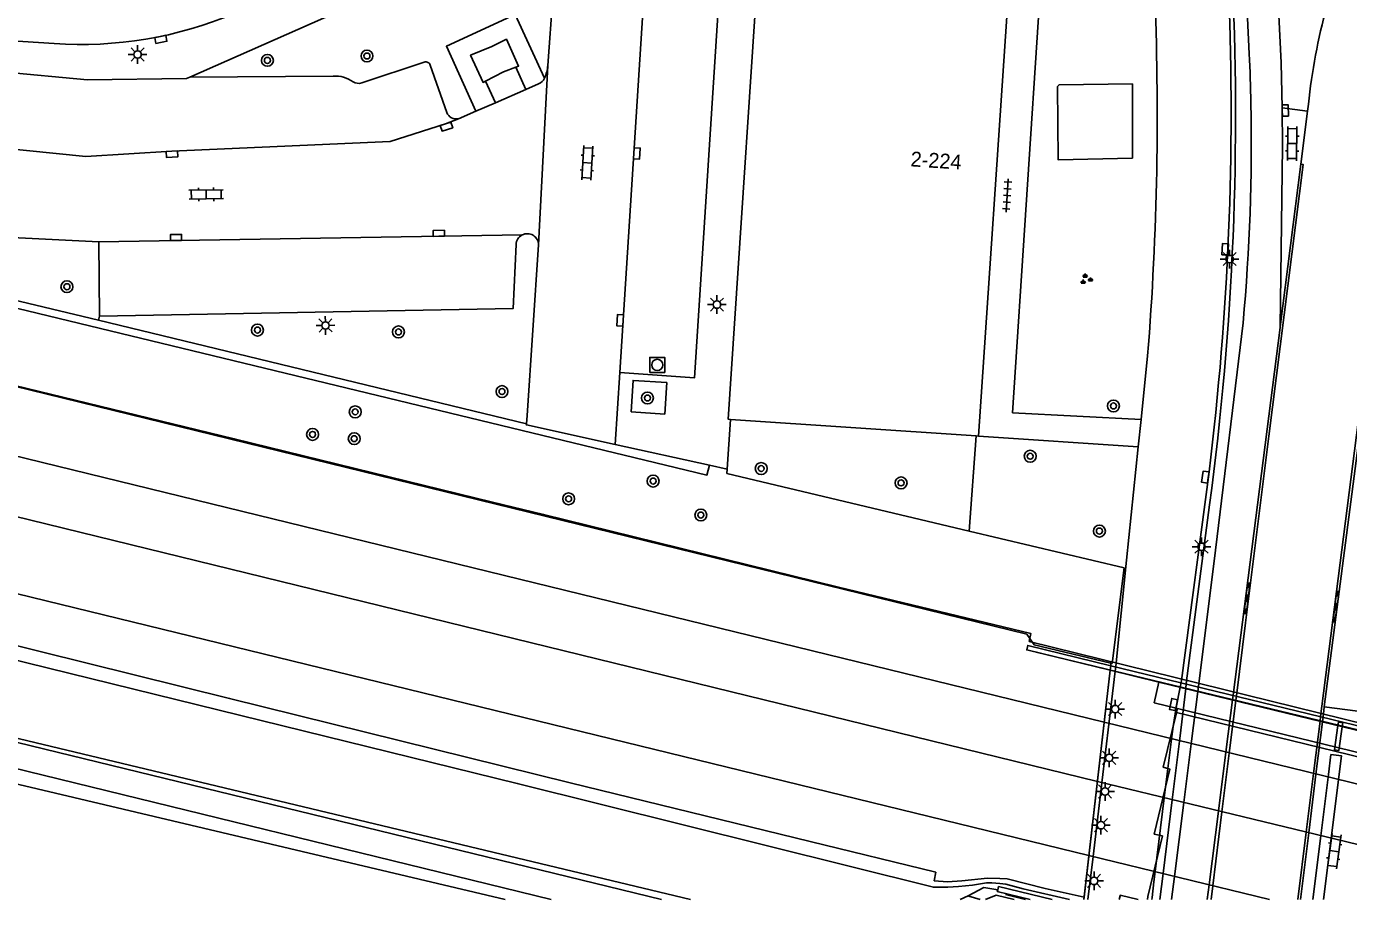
# Model space of a CAD drawing. Extents: x 132998 to 136004, y 396998 to 398512.
# Drawn here: x 133226.6 to 133315.3, y 397000 to 397058.6 of the extents above; entities that cross this region are included whole.
import ezdxf

# ---------------------------------------------------------------- set-up
doc = ezdxf.new("R2010")
doc.units = 0
for name, color, linetype in [('gg-afsc-hekwerk', 7, 'Continuous'), ('gg-afsc-muur', 7, 'Continuous'), ('gg-anno-huisnummerreeks BGT', 7, 'Continuous'), ('gg-aspt-spoorlijn', 7, 'Continuous'), ('gg-bbg-hoofdgebouw', 7, 'Continuous'), ('gg-bbg-lage trafo', 7, 'Continuous'), ('gg-bbg-pilaar viaduct of brug', 7, 'Continuous'), ('gg-knt-BGT kruinlijn', 7, 'Continuous'), ('gg-knt-bovenkant onderkant talud', 7, 'Continuous'), ('gg-knt-bronhoudergrens', 7, 'Continuous'), ('gg-knt-verharding', 7, 'Continuous'), ('gg-knt-verharding niveau 01', 7, 'Continuous'), ('gg-knt-verharding nz', 7, 'Continuous'), ('gg-kntw-beschoeiing', 7, 'Continuous'), ('gt-grn-afwateringsgoot', 7, 'Continuous'), ('gt-grn-bladgrens', 7, 'Continuous'), ('gt-grn-groengrens', 7, 'Continuous'), ('gt-grn-weggrens', 7, 'Continuous'), ('gt-symb-afwateringsgoot', 7, 'Continuous'), ('gt-symb-boom', 7, 'Continuous'), ('gt-symb-groenvak', 7, 'Continuous'), ('gt-symb-klinker verharding', 7, 'Continuous'), ('gt-symb-kolk', 7, 'Continuous'), ('gt-symb-lichtmast', 7, 'Continuous'), ('gt-symb-rioolschacht', 7, 'Continuous'), ('gt-symb-tegel verharding', 7, 'Continuous'), ('gx-grn-maaiveld', 7, 'Continuous'), ('gx-knt-lijn weginrichtingselement', 7, 'Continuous')]:
    doc.layers.add(name, color=color, linetype=linetype)

# ---------------------------------------------------------------- blocks, each defined once
blk = doc.blocks.new('gt0-BOOM')
at = {"layer": 'gt-symb-boom'}
for radius in [0.4, 0.2]:
    blk.add_circle((0, 0), radius, dxfattribs=at)
blk = doc.blocks.new('gt0-LMAST')
at = {"layer": 'gt-symb-lichtmast'}
for p, q in [((-0.182, 0.173), (-0.447, 0.438)), ((-0.005, 0.246), (-0.005, 0.621)), ((0.172, 0.173), (0.437, 0.438)), ((-0.255, -0.004), (-0.63, -0.004)), ((-0.182, -0.181), (-0.447, -0.446)), ((-0.005, -0.254), (-0.005, -0.629)), ((0.437, -0.446), (0.172, -0.181)), ((0.245, -0.004), (0.62, -0.004))]:
    blk.add_line(p, q, dxfattribs=at)
blk.add_circle((-0.005, -0.004), 0.25, dxfattribs=at)
blk = doc.blocks.new('gt0-KOLK')
at = {"layer": 'gt-symb-kolk'}
blk.add_lwpolyline([(0, 0), (0.375, 0), (0.375, 0.4), (-0.375, 0.4), (-0.375, 0), (0, 0)], dxfattribs=at)
blk = doc.blocks.new('gt0-KL1')
at = {"layer": 'gt-symb-klinker verharding'}
for p, q in [((-1.15, 0.3), (1.15, 0.3)), ((-1, -0.3), (-1, 0.3)), ((-0.5, 0.3), (-0.5, 0.45)), ((0, -0.3), (0, 0.3)), ((0.5, 0.3), (0.5, 0.45)), ((1, -0.3), (1, 0.3)), ((-1.15, -0.3), (1.15, -0.3)), ((-0.5, -0.45), (-0.5, -0.3)), ((0.5, -0.45), (0.5, -0.3))]:
    blk.add_line(p, q, dxfattribs=at)
blk = doc.blocks.new('gt0-RS')
at = {"layer": 'gt-symb-rioolschacht'}
blk.add_lwpolyline([(-0.5, -0.5), (0.5, -0.5), (0.5, 0.5), (-0.5, 0.5)], close=True, dxfattribs=at)
blk.add_circle((0, 0), 0.375, dxfattribs=at)
blk = doc.blocks.new('gt0-TEG1')
at = {"layer": 'gt-symb-tegel verharding'}
for p, q in [((-1.125, 0), (1.125, 0)), ((-0.9, -0.25), (-0.9, 0.25)), ((-0.45, -0.25), (-0.45, 0.25)), ((0, -0.25), (0, 0.25)), ((0.45, -0.25), (0.45, 0.25)), ((0.9, -0.25), (0.9, 0.25))]:
    blk.add_line(p, q, dxfattribs=at)
blk = doc.blocks.new('gt0-GRVAK')
at = {"layer": 'gt-symb-groenvak'}
for p, q in [((-0.11, 0.189), (-0.228, 0.24)), ((-0.182, 0.153), (0.088, 0.153)), ((-0.091, 0.211), (-0.156, 0.322)), ((-0.047, 0.214), (-0.047, 0.393)), ((-0.004, 0.211), (0.061, 0.322)), ((0.015, 0.189), (0.133, 0.24)), ((0.262, -0.052), (0.197, 0.059)), ((0.305, -0.049), (0.305, 0.13)), ((0.349, -0.052), (0.414, 0.059)), ((-0.245, -0.228), (-0.363, -0.177)), ((-0.318, -0.264), (-0.047, -0.264)), ((-0.226, -0.206), (-0.291, -0.095)), ((-0.183, -0.203), (-0.183, -0.024)), ((-0.139, -0.206), (-0.074, -0.095)), ((-0.12, -0.228), (-0.002, -0.177)), ((0.243, -0.074), (0.125, -0.023)), ((0.17, -0.11), (0.441, -0.11)), ((0.368, -0.074), (0.486, -0.023))]:
    blk.add_line(p, q, dxfattribs=at)
blk = doc.blocks.new('gt0-AFWGT_1')
at = {"layer": 'gt-symb-afwateringsgoot'}
for p, q in [((-1.076, 0), (-0.726, 0)), ((-0.225, 0), (0.225, 0)), ((0.725, 0), (1.075, 0))]:
    blk.add_line(p, q, dxfattribs=at)
for points in [[(-0.726, 0.075), (-0.225, 0.075), (-0.225, -0.075), (-0.726, -0.075)], [(0.225, 0.075), (0.725, 0.075), (0.725, -0.075), (0.225, -0.075)]]:
    blk.add_lwpolyline(points, close=True, dxfattribs=at)

msp = doc.modelspace()

# ---------------------------------------------------------------- linework, layer by layer
at = {"layer": 'gg-afsc-hekwerk'}
for p, q in [((133273.86, 397032.22), (133273.639, 397028.884)), ((133273.86, 397032.22), (133273.639, 397028.884)), ((133289.871, 397024.728), (133290.35, 397031.11)), ((133289.871, 397024.728), (133290.35, 397031.11)), ((133273.639, 397028.884), (133273.619, 397028.578)), ((133273.639, 397028.884), (133273.619, 397028.578)), ((133273.619, 397028.578), (133289.871, 397024.728)), ((133273.619, 397028.578), (133289.871, 397024.728)), ((133300.273, 397022.263), (133289.871, 397024.728)), ((133300.273, 397022.263), (133289.871, 397024.728)), ((133300.273, 397022.263), (133299.472, 397015.831)), ((133300.273, 397022.263), (133299.472, 397015.831))]:
    msp.add_line(p, q, dxfattribs=at)
msp.add_lwpolyline([(133000, 397065.503), (133076.543, 397046.781), (133180.571, 397021.692), (133271.17, 397000)], dxfattribs=at)
msp.add_lwpolyline([(133000, 397065.503), (133076.543, 397046.781), (133180.571, 397021.692), (133271.17, 397000)], dxfattribs=at)
at = {"layer": 'gg-afsc-muur'}
for p, q in [((133293.74, 397017.818), (133163.478, 397049.706)), ((133293.74, 397017.818), (133163.478, 397049.706)), ((133305.964, 397028.691), (133304.112, 397014.708)), ((133304.438, 397014.491), (133305.998, 397026.478)), ((133304.411, 397014.163), (133303.997, 397010.814)), ((133304.025, 397014.258), (133304.094, 397014.575)), ((133304.112, 397014.708), (133304.094, 397014.575)), ((133304.438, 397014.491), (133304.411, 397014.163)), ((133302.958, 397006.824), (133303.477, 397010.94)), ((133303.49, 397006.695), (133303.997, 397010.814)), ((133302.343, 397001.873), (133302.958, 397006.824)), ((133303.49, 397006.695), (133302.878, 397001.741)), ((133302.663, 397000), (133302.878, 397001.741)), ((133302.122, 397000), (133302.138, 397000.144))]:
    msp.add_line(p, q, dxfattribs=at)
for points in [[(133303.477, 397010.94), (133303.562, 397011.622), (133303.748, 397012.891), (133304.025, 397014.258)], [(133302.138, 397000.144), (133302.257, 397001.18), (133302.343, 397001.873)]]:
    msp.add_lwpolyline(points, dxfattribs=at)
for centre, radius, start, end in [((133111.617, 397052.578), 196.126, 352.35237, 2.92485), ((133109.549, 397052.867), 197.897, 352.98297, 2.3061)]:
    msp.add_arc(centre, radius, start, end, dxfattribs=at)
at = {"layer": 'gg-aspt-spoorlijn'}
for p, q in [((133000, 397081.027), (133298.474, 397007.929)), ((133298.931, 397011.894), (133329.558, 397004.427)), ((133298.474, 397007.929), (133329.088, 397000.493)), ((133297.901, 397002.954), (133310.014, 397000))]:
    msp.add_line(p, q, dxfattribs=at)
for points in [[(133000, 397085.097), (133023.788, 397079.291), (133131.609, 397052.829), (133298.931, 397011.894)], [(133000, 397075.839), (133096.746, 397052.101), (133297.901, 397002.954)]]:
    msp.add_lwpolyline(points, dxfattribs=at)
at = {"layer": 'gg-bbg-hoofdgebouw'}
for p, q in [((133292.952, 397067.526), (133290.5, 397031.1)), ((133273.86, 397032.22), (133290.35, 397031.11)), ((133290.35, 397031.11), (133290.5, 397031.1))]:
    msp.add_line(p, q, dxfattribs=at)
msp.add_lwpolyline([(133276.14, 397069.07), (133273.71, 397032.23), (133273.86, 397032.22)], dxfattribs=at)
at = {"layer": 'gg-bbg-lage trafo'}
for points in [[(133259.457, 397055.854), (133259.647, 397055.925), (133258.834, 397057.729), (133257.856, 397057.237), (133256.43, 397056.648), (133257.26, 397054.831), (133257.433, 397054.921)], [(133257.433, 397054.921), (133258.635, 397055.545), (133259.457, 397055.854)]]:
    msp.add_lwpolyline(points, dxfattribs=at)
at = {"layer": 'gg-bbg-pilaar viaduct of brug'}
for p, q in [((133313.466, 397004.274), (133313.979, 397008.401)), ((133314.161, 397004.106), (133314.674, 397008.233)), ((133312.935, 397000), (133313.466, 397004.274)), ((133313.651, 397000), (133314.161, 397004.106))]:
    msp.add_line(p, q, dxfattribs=at)
for points in [[(133314.611, 397011.673), (133314.377, 397010.05), (133314.674, 397010.007), (133314.904, 397011.601)], [(133314.611, 397011.673), (133314.644, 397011.9), (133314.941, 397011.857), (133314.904, 397011.601)], [(133314.674, 397008.233), (133314.849, 397009.645), (133314.145, 397009.733), (133313.979, 397008.401)]]:
    msp.add_lwpolyline(points, dxfattribs=at)
at = {"layer": 'gg-knt-BGT kruinlijn'}
msp.add_lwpolyline([(133186.49, 397000), (133184.153, 397003.644), (133183.522, 397004.975), (133183.374, 397006.047), (133183.716, 397010.358), (133184.658, 397013.497), (133185.793, 397015.048), (133187.27, 397015.648), (133189.046, 397016.11), (133191.787, 397015.743), (133224.019, 397008.202), (133258.747, 397000)], dxfattribs=at)
at = {"layer": 'gg-knt-bovenkant onderkant talud'}
msp.add_line((133291.681, 397000.298), (133292.893, 397000), dxfattribs=at)
at = {"layer": 'gg-knt-bronhoudergrens'}
msp.add_line((133299.387, 397015.852), (133299.472, 397015.831), dxfattribs=at)
msp.add_lwpolyline([(133293.74, 397017.818), (133294.231, 397017.101), (133299.387, 397015.852)], dxfattribs=at)
at = {"layer": 'gg-knt-verharding'}
for p, q in [((133307.747, 397075.693), (133308.664, 397056.751)), ((133261.606, 397055.966), (133262.269, 397064.966)), ((133257.999, 397064.195), (133237.59, 397055.191)), ((133292.79, 397032.65), (133294.805, 397063.341)), ((133219.287, 397058.019), (133228.484, 397057.43)), ((133249.131, 397054.792), (133253.321, 397056.187)), ((133253.723, 397055.994), (133254.834, 397052.81)), ((133260.134, 397054.35), (133259.457, 397055.854)), ((133237.59, 397055.191), (133247.208, 397055.244)), ((133258.088, 397053.462), (133257.433, 397054.921)), ((133258.088, 397053.462), (133260.134, 397054.35)), ((133260.134, 397054.35), (133260.99, 397054.734)), ((133256.775, 397052.901), (133258.088, 397053.462)), ((133312.568, 397052.89), (133312.627, 397053.366)), ((133255.606, 397052.389), (133256.775, 397052.901)), ((133312.568, 397052.89), (133310.87, 397053.129)), ((133312.133, 397049.349), (133312.568, 397052.89)), ((133310.739, 397038.43), (133312.133, 397049.349)), ((133231.483, 397044.133), (133231.53, 397039.14)), ((133260.213, 397032.483), (133260.983, 397043.922)), ((133301.845, 397036.477), (133301.403, 397032.218)), ((133266.131, 397030.538), (133266.441, 397035.367)), ((133260.175, 397031.922), (133260.213, 397032.483)), ((133292.79, 397032.65), (133301.403, 397032.218)), ((133301.403, 397032.218), (133301.213, 397030.379)), ((133290.5, 397031.1), (133301.213, 397030.379)), ((133316.126, 397031.677), (133313.693, 397012.921)), ((133272.447, 397029.147), (133266.131, 397030.538)), ((133273.639, 397028.884), (133272.447, 397029.147)), ((133313.693, 397012.921), (133313.61, 397012.245)), ((133313.693, 397012.921), (133317.712, 397012.407))]:
    msp.add_line(p, q, dxfattribs=at)
for points in [[(133309.826, 397076.336), (133309.845, 397075.81), (133310.793, 397056.152), (133310.87, 397053.129)], [(133000, 397064.614), (133037.586, 397055.47), (133127.872, 397033.617), (133162.421, 397025.507), (133179.236, 397021.338), (133188.591, 397019.265), (133225.122, 397010.768), (133269.223, 397000)], [(133268.243, 397063.458), (133273.262, 397063.183), (133271.438, 397035.006), (133266.441, 397035.367)], [(133256.775, 397052.901), (133254.808, 397057.253), (133259.408, 397059.39), (133261.382, 397055.116)], [(133237.59, 397055.191), (133237.36, 397055.09), (133230.74, 397055), (133201.968, 397057.692), (133201.842, 397056.086)], [(133310.87, 397053.129), (133310.902, 397050.534), (133310.739, 397038.43)], [(133231.483, 397044.133), (133224.75, 397044.46), (133197.779, 397047.017)], [(133231.53, 397039.14), (133259.28, 397039.65), (133259.48, 397043.951)], [(133308.248, 397038.702), (133306.405, 397023.437), (133305.25, 397014.292)], [(133307.591, 397013.719), (133310.732, 397038.377), (133310.739, 397038.43)], [(133267.196, 397032.719), (133267.331, 397034.835), (133269.582, 397034.687), (133269.447, 397032.571), (133267.196, 397032.719)], [(133266.131, 397030.538), (133260.17, 397031.85), (133260.175, 397031.922)], [(133301.213, 397030.379), (133300.425, 397022.783), (133299.711, 397015.65)], [(133180.087, 397016.001), (133180.812, 397017.737), (133181.256, 397018.408), (133182.146, 397018.674), (133187.675, 397017.479), (133224.542, 397009.119), (133261.83, 397000)]]:
    msp.add_lwpolyline(points, dxfattribs=at)
for centre, radius, start, end in [((133098.931, 397052.639), 203.556, 355.44591, 2.44072), ((133230.246, 397084.159), 26.787, 266.22854, 292.66688), ((133354.833, 397048.833), 42.449, 164.89429, 173.86958), ((133176.205, 397050.826), 132.592, 1.12284, 2.56129), ((133253.428, 397055.894), 0.312, 18.66912, 110.0396), ((133259.234, 397056.136), 2.378, 334.58451, 355.88856), ((133247.381, 397053.292), 1.959, 53.683, 95.05164), ((133260.773, 397055.349), 0.652, 289.45763, 339.06194), ((133248.925, 397055.494), 0.732, 238.36903, 286.37808), ((133174.865, 397050.811), 133.932, 354.81282, 1.11802), ((133255.472, 397053.062), 0.686, 201.55291, 281.23657), ((133260.229, 397043.931), 0.75, 117.77458, 178.45526), ((133260.232, 397043.93), 0.751, 359.36848, 117.92801)]:
    msp.add_arc(centre, radius, start, end, dxfattribs=at)
at = {"layer": 'gg-knt-verharding niveau 01'}
for p, q in [((133297.561, 397000), (133299.333, 397015.385)), ((133299.368, 397015.691), (133299.333, 397015.385)), ((133299.333, 397015.385), (133302.59, 397014.591)), ((133299.368, 397015.691), (133330.01, 397008.22)), ((133326.896, 397008.665), (133302.59, 397014.591)), ((133303.853, 397012.822), (133303.784, 397012.541)), ((133303.784, 397012.541), (133325.625, 397007.215)), ((133303.853, 397012.822), (133325.915, 397007.442))]:
    msp.add_line(p, q, dxfattribs=at)
for points in [[(133302.59, 397014.591), (133302.292, 397013.202), (133303.853, 397012.822)], [(133303.784, 397012.541), (133303.785, 397012.54), (133302.886, 397008.883)], [(133302.886, 397008.883), (133303.329, 397008.756), (133302.287, 397004.399), (133302.84, 397004.267), (133301.866, 397000.21), (133301.833, 397000)], [(133299.933, 397000), (133299.992, 397000.259), (133300.001, 397000.295), (133301.208, 397000)]]:
    msp.add_lwpolyline(points, dxfattribs=at)
at = {"layer": 'gg-knt-verharding nz'}
for p, q in [((133266.441, 397035.367), (133268.243, 397063.458)), ((133230.616, 397049.869), (133201.58, 397052.738)), ((133231.483, 397044.133), (133259.88, 397044.594)), ((133299.671, 397015.32), (133299.269, 397011.957)), ((133299.711, 397015.65), (133299.671, 397015.32)), ((133305.25, 397014.292), (133305.209, 397013.968)), ((133305.209, 397013.968), (133304.786, 397010.623)), ((133307.124, 397010.058), (133307.549, 397013.397)), ((133307.549, 397013.397), (133307.591, 397013.719)), ((133299.269, 397011.957), (133298.776, 397007.84)), ((133313.571, 397011.927), (133313.161, 397008.599)), ((133313.61, 397012.245), (133313.571, 397011.927)), ((133304.786, 397010.623), (133304.266, 397006.507)), ((133306.599, 397005.94), (133307.124, 397010.058)), ((133313.161, 397008.599), (133312.652, 397004.472)), ((133298.776, 397007.84), (133298.183, 397002.894)), ((133304.266, 397006.507), (133303.64, 397001.554)), ((133305.968, 397000.983), (133306.599, 397005.94)), ((133312.102, 397000), (133312.652, 397004.472)), ((133297.837, 397000), (133298.183, 397002.894)), ((133303.444, 397000), (133303.64, 397001.554)), ((133305.843, 397000), (133305.968, 397000.983))]:
    msp.add_line(p, q, dxfattribs=at)
msp.add_lwpolyline([(133230.616, 397049.869), (133236.386, 397050.212), (133251.023, 397050.871), (133254.751, 397052.057), (133255.606, 397052.389)], dxfattribs=at)
at = {"layer": 'gg-kntw-beschoeiing'}
for points in [[(133293.908, 397017.321), (133294.015, 397017.844), (133281.102, 397020.96), (133261.323, 397025.845), (133257.889, 397026.669), (133240.574, 397030.918), (133215.176, 397037.087), (133173.826, 397047.249), (133156.339, 397051.485), (133065.484, 397073.822), (133055.258, 397076.278), (133002.984, 397089.089), (133000, 397089.82)], [(133293.908, 397017.321), (133323.109, 397010.123), (133335.732, 397007.126)]]:
    msp.add_lwpolyline(points, dxfattribs=at)
at = {"layer": 'gt-grn-afwateringsgoot'}
for p, q in [((133307.341, 397010.006), (133307.757, 397013.346)), ((133307.757, 397013.346), (133307.797, 397013.669)), ((133312.998, 397008.638), (133313.411, 397011.966)), ((133313.411, 397011.966), (133313.451, 397012.284)), ((133306.829, 397005.885), (133307.341, 397010.006)), ((133312.485, 397004.512), (133312.998, 397008.638)), ((133306.212, 397000.923), (133306.829, 397005.885)), ((133311.924, 397000), (133312.485, 397004.512)), ((133306.098, 397000), (133306.212, 397000.923))]:
    msp.add_line(p, q, dxfattribs=at)
for points in [[(133307.797, 397013.669), (133308.406, 397018.571), (133309.974, 397031.101), (133312.283, 397049.315), (133312.133, 397049.349)], [(133313.451, 397012.284), (133313.537, 397012.976), (133316.206, 397033.953)]]:
    msp.add_lwpolyline(points, dxfattribs=at)
at = {"layer": 'gt-grn-bladgrens'}
for points in [[(133034.543, 397063.022), (133070.333, 397054.424), (133117.072, 397042.894), (133141.925, 397036.619), (133190.839, 397024.702), (133259.561, 397007.794), (133287.473, 397000.823), (133288.445, 397000.833), (133289.162, 397000.874), (133290.088, 397000.969), (133291.041, 397001.116), (133291.395, 397001.114), (133291.936, 397001.083), (133292.338, 397001.031), (133293.506, 397000.709), (133296.595, 397000)], [(133137.097, 397038.789), (133161.496, 397032.818), (133168.348, 397031.137), (133183.76, 397027.389), (133208.835, 397021.229), (133224.286, 397017.445), (133240.265, 397013.495), (133263.107, 397007.834), (133279.21, 397003.889), (133287.635, 397001.837), (133287.532, 397001.259), (133288.413, 397001.182), (133289.388, 397001.259), (133291.1, 397001.445), (133291.94, 397001.424), (133292.43, 397001.388), (133294.97, 397000.752), (133297.579, 397000.161)], [(133297.561, 397000), (133297.578, 397000.152), (133297.579, 397000.161)]]:
    msp.add_lwpolyline(points, dxfattribs=at)
at = {"layer": 'gt-grn-groengrens'}
for p, q in [((133197.779, 397047.017), (133231.465, 397038.868)), ((133231.53, 397039.14), (133231.465, 397038.868)), ((133231.465, 397038.868), (133260.175, 397031.922))]:
    msp.add_line(p, q, dxfattribs=at)
for points in [[(133164.573, 397054.536), (133272.285, 397028.478), (133272.447, 397029.147)], [(133295.79, 397054.557), (133295.905, 397054.671), (133300.826, 397054.729), (133300.826, 397049.749), (133295.848, 397049.635), (133295.79, 397054.557)]]:
    msp.add_lwpolyline(points, dxfattribs=at)
at = {"layer": 'gt-grn-weggrens'}
msp.add_line((133260.983, 397043.922), (133261.606, 397055.966), dxfattribs=at)
at = {"layer": 'gx-grn-maaiveld'}
for p, q in [((133299.333, 397015.385), (133297.579, 397000.161)), ((133299.387, 397015.852), (133299.368, 397015.691)), ((133289.274, 397000), (133289.804, 397000.241)), ((133289.804, 397000.241), (133290.849, 397000.819)), ((133291.788, 397000.647), (133290.849, 397000.819)), ((133290.974, 397000), (133291.681, 397000.298))]:
    msp.add_line(p, q, dxfattribs=at)
for points in [[(133299.368, 397015.691), (133293.806, 397017.048), (133293.733, 397016.751), (133299.333, 397015.385)], [(133291.788, 397000.647), (133291.842, 397000.872), (133295.451, 397000)], [(133289.804, 397000.241), (133289.858, 397000.228), (133290.602, 397000)], [(133291.788, 397000.647), (133291.76, 397000.531), (133293.957, 397000)]]:
    msp.add_lwpolyline(points, dxfattribs=at)
at = {"layer": 'gx-knt-lijn weginrichtingselement'}
for p, q in [((133294.361, 397016.596), (133335.685, 397006.639)), ((133292.319, 397000.329), (133293.661, 397000))]:
    msp.add_line(p, q, dxfattribs=at)

# ---------------------------------------------------------------- block references
at = {"layer": 'gt-symb-afwateringsgoot'}
for p, xscale, yscale, rotation in [((133308.512, 397020.215), 0.9999990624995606, 0.9999990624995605, 82.86254697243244), ((133314.473, 397019.651), 1.000001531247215, 1.0000015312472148, 82.74706373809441)]:
    msp.add_blockref('gt0-AFWGT_1', p, dxfattribs=dict(at, xscale=xscale, yscale=yscale, rotation=rotation))
at = {"layer": 'gt-symb-boom'}
for p in [(133249.477, 397056.603), (133242.797, 397056.309), (133229.35, 397041.123), (133242.132, 397038.214), (133251.59, 397038.086), (133258.535, 397034.087), (133268.292, 397033.655), (133248.686, 397032.724), (133299.552, 397033.12), (133245.827, 397031.211), (133248.621, 397030.925), (133293.967, 397029.746), (133275.923, 397028.921), (133268.674, 397028.081), (133285.305, 397027.957), (133263.005, 397026.889), (133271.873, 397025.802), (133298.609, 397024.725)]:
    msp.add_blockref('gt0-BOOM', p, dxfattribs=at)
at = {"layer": 'gt-symb-groenvak'}
msp.add_blockref('gt0-GRVAK', (133297.705, 397041.619), dxfattribs=at)
at = {"layer": 'gt-symb-klinker verharding'}
for p, rotation in [((133311.548, 397050.727), 89.4270613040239), ((133264.258, 397049.43), 86.3307459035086), ((133238.69, 397047.313), 0.9166542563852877), ((133314.365, 397003.245), 82.24257421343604)]:
    msp.add_blockref('gt0-KL1', p, dxfattribs=dict(at, rotation=rotation))
at = {"layer": 'gt-symb-kolk'}
for p, rotation in [((133235.607, 397057.914), -168.4653793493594), ((133310.875, 397052.941), -88.56790381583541), ((133254.751, 397052.057), -162.34847766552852), ((133236.386, 397050.212), -176.59230947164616), ((133267.382, 397050.076), -93.6692540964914), ((133236.669, 397044.224), 0.8020885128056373), ((133254.302, 397044.504), 0.973934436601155), ((133307.246, 397043.628), 87.36361809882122), ((133266.655, 397038.854), 86.3879250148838), ((133305.913, 397028.319), 82.18581914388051), ((133303.78, 397013.044), 78.17329607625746)]:
    msp.add_blockref('gt0-KOLK', p, dxfattribs=dict(at, rotation=rotation))
at = {"layer": 'gt-symb-lichtmast'}
for p in [(133234.095, 397056.708), (133307.35, 397042.98), (133272.957, 397039.926), (133305.466, 397023.678), (133299.676, 397012.786), (133299.274, 397009.514), (133298.994, 397007.252), (133298.718, 397004.991), (133298.257, 397001.256)]:
    msp.add_blockref('gt0-LMAST', p, dxfattribs=at)
at = {"layer": 'gt-symb-lichtmast', "rotation": -178.9687873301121}
msp.add_blockref('gt0-LMAST', (133246.689, 397038.518), dxfattribs=at)
at = {"layer": 'gt-symb-rioolschacht'}
msp.add_blockref('gt0-RS', (133268.95, 397035.876), dxfattribs=at)
at = {"layer": 'gt-symb-tegel verharding', "rotation": -93.78359025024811}
msp.add_blockref('gt0-TEG1', (133292.422, 397047.244), dxfattribs=at)

# ---------------------------------------------------------------- texts
at = {"layer": 'gg-anno-huisnummerreeks BGT'}
msp.add_text('2-224', height=1, rotation=356.2, dxfattribs=at).set_placement((133285.919, 397049.202))

doc.saveas('drawing.dxf')
